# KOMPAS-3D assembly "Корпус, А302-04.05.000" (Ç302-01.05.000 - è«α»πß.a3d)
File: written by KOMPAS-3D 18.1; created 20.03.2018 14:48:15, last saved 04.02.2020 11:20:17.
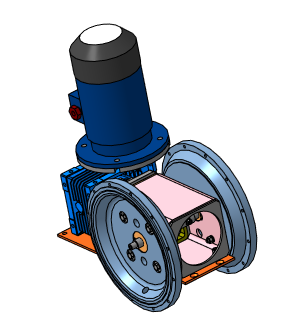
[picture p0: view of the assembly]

Document properties: Автор: Милов; Полное имя файла: D:\Мембранные насосы\Мембранный электропривод\А302-00.00.000 - ASTRA-302 (МЭ200) новая для Караби\3Д ПВХ\А302-01.05.000 - Корпус.a3d

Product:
- Part/product: Корпус  | designation А302-04.05.000  | pos. 0
    Масса: 37.0586
    Раздел спецификации: Сборочные единицы
    Форматы листов документа: A3
    source file: ..\А302-04.00.000 - Мембранный насос ASTRA-302-PP\А302-04.05.000 - Корпус.cdw
  - Component [standard]: Винт с потайной головкой и шестигранным углублением под ключГОСТ Р ИСО 10642-М4x20-8.8-A3J  | pos. 43  | Материал: Сталь (density 1000 kg/m3); Масса: 0.000288344; Раздел спецификации: Стандартные изделия; additional columns: ГОСТ Р ИСО 10642-2012; М4 x 20 - 8.8 - A3J; Сталь
  - Component [standard]: Винт с потайной головкой и шестигранным углублением под ключГОСТ Р ИСО 10642-М4x20-8.8-A3J  | pos. 42  | Материал: Сталь (density 1000 kg/m3); Масса: 0.000288344; Раздел спецификации: Стандартные изделия; additional columns: ГОСТ Р ИСО 10642-2012; М4 x 20 - 8.8 - A3J; Сталь
  - Component [standard]: Болт М8-6gx35.58.019 ГОСТ 7805-70  | qty 4  | pos. 8  | Материал: Сталь 20 ГОСТ 1050-2013 (density 1000 kg/m3); Масса: 0.01909; Раздел спецификации: Стандартные изделия; Рассекать на разрезах: no; additional columns: Сталь 20 ГОСТ 1050-2013
  - Component [detail]: Основание  | designation А302-04.05.001  | qty 2  | pos. 4  | Материал: Полипропилен  ГОСТ 26996-86 (density 900 kg/m3); Масса: 1.33492; Раздел спецификации: Детали; Форматы листов документа: A3; source file: ..\3Д\А302-00.05.001 - Основание.m3d, ..\А302-05.00.000 - Мембранный насос ASTRA-302-PVC\А302-05.05.001 - Основание.cdw, ..\Чертежи ПВХ\А302-02.05.001 - Основание.cdw, ..\Чертежи Полипропилен\А302-03.05.001 - Основание.cdw
  - Component [detail]: Ловитель  | designation А302-01.05.002  | qty 2  | pos. 5  | Материал: Фторопласт-4  ГОСТ 10007-80 Е (density 2200 kg/m3); Масса: 0.0582106; Раздел спецификации: Детали; Форматы листов документа: A3; source file: А302-01.05.002 - Ловитель.cdw, Отработка\А302-01.05.002 - Ловитель.m3d
  - Component [assembly]: Мотор-редуктор  | designation А302-04.20.000  | pos. 53  | Масса: 34.037; Раздел спецификации: Сборочные единицы; Форматы листов документа: A3; source file: ..\А302-04.00.000 - Мембранный насос ASTRA-302-PP\А302-04.20.000 СБ - Мотор-редуктор.cdw, Отработка\А302-01.20.000 - Мотор-редуктор.a3d
  - Component [standard]: Болт М8-6gx35.58.019 ГОСТ 7805-70  | pos. 457  | Материал: Сталь 20 ГОСТ 1050-2013 (density 1000 kg/m3); Масса: 0.01909; Раздел спецификации: Стандартные изделия; Рассекать на разрезах: no
  - Component [standard]: Болт М8-6gx35.58.019 ГОСТ 7805-70  | pos. 458  | Материал: Сталь 20 ГОСТ 1050-2013 (density 1000 kg/m3); Масса: 0.01909; Раздел спецификации: Стандартные изделия; Рассекать на разрезах: no
  - Component [standard]: Болт М8-6gx35.58.019 ГОСТ 7805-70  | pos. 459  | Материал: Сталь 20 ГОСТ 1050-2013 (density 1000 kg/m3); Масса: 0.01909; Раздел спецификации: Стандартные изделия; Рассекать на разрезах: no
  - Component [standard]: Болт М8-6gx35.58.019 ГОСТ 7805-70  | pos. 460  | Материал: Сталь 20 ГОСТ 1050-2013 (density 1000 kg/m3); Масса: 0.01909; Раздел спецификации: Стандартные изделия; Рассекать на разрезах: no
- Part/product: Корпус  | designation А302-03.05.000  | pos. 0
    Масса: 31.4728
    Раздел спецификации: Сборочные единицы
    Форматы листов документа: A3
    source file: ..\Чертежи Полипропилен\А302-03.05.000 - Корпус.cdw
  - Component [assembly]: Мотор-редуктор  | designation А302-02.20.000  | pos. 53  | Масса: 27.8186; Раздел спецификации: Сборочные единицы; Форматы листов документа: 2xA3; Примечание: @100~)2xA3; source file: Отработка\А302-01.20.000 - Мотор-редуктор.a3d
  - Component [detail]: Ловитель  | designation А302-01.05.002  | qty 2  | pos. 5  | Материал: Фторопласт-4  ГОСТ 10007-80 Е (density 2200 kg/m3); Масса: 0.0582106; Раздел спецификации: Детали; Форматы листов документа: A3; source file: А302-01.05.002 - Ловитель.cdw, Отработка\А302-01.05.002 - Ловитель.m3d
  - Component [detail]: Основание  | designation А302-03.05.001  | qty 2  | pos. 4  | Материал: Полипропилен  ГОСТ 26996-86 (density 900 kg/m3); Масса: 1.33086; Раздел спецификации: Детали; Форматы листов документа: A3; source file: ..\3Д\А302-00.05.001 - Основание.m3d
  - Component [detail]: Фиксатор  | designation А302-01.05.012  | pos. 1  | Раздел спецификации: Детали; Форматы листов документа: A3; source file: А302-01.05.012 - Фиксатор.cdw, Отработка\Фиксатор.m3d
  - Component [detail]: Упор  | designation А302-01.05.014  | qty 2  | pos. 1  | Материал: Сталь 20  ГОСТ 1050-2013 (density 0 kg/m3); Раздел спецификации: Детали; Форматы листов документа: A3; source file: А302-01.05.014 - Упор.cdw, Отработка\Упор-1.m3d
  - Component [detail]: Ловитель  | designation А302-01.05.011  | pos. 1  | Материал: Сталь 40  ГОСТ 1050-2013 (density 0 kg/m3); Раздел спецификации: Детали; Форматы листов документа: A4; source file: А302-01.05.011 - Ловитель.cdw, А302-01.05.011 - Ловитель.m3d
  - Component [detail]: Фиксатор  | designation А302-01.05.015  | pos. 198  | Раздел спецификации: Детали; Форматы листов документа: A4; source file: А302-01.05.015 - Фиксатор.cdw, А302-01.05.015 - Фиксатор.m3d
  - Component [detail]: Фиксатор  | designation А302-01.05.015  | pos. 189  | Раздел спецификации: Детали; Форматы листов документа: A4; source file: А302-01.05.015 - Фиксатор.cdw, А302-01.05.015 - Фиксатор.m3d
- Part/product: Корпус  | designation А302-00.05.000  | pos. 0
    Масса: 33.4594
    Раздел спецификации: Сборочные единицы
    Форматы листов документа: A3
  - Component [assembly]: Мотор-редуктор  | designation А302-01.20.000  | pos. 0  | Масса: 27.8253; Раздел спецификации: Сборочные единицы; Форматы листов документа: 2xA3; Примечание: @100~)2xA3; source file: А302-01.20.000 - Мотор-редуктор.cdw, Отработка\А302-01.20.000 - Мотор-редуктор.a3d
  - Component [detail]: Ловитель  | designation А302-01.05.002  | qty 2  | pos. 5  | Материал: Фторопласт-4  ГОСТ 10007-80 Е (density 2200 kg/m3); Масса: 0.0582106; Раздел спецификации: Детали; Форматы листов документа: A3; source file: А302-01.05.002 - Ловитель.cdw, Отработка\А302-01.05.002 - Ловитель.m3d
  - Component [detail]: Основание  | designation А302-00.05.001  | qty 2  | pos. 4  | Материал: Полипропилен  ГОСТ 26996-86 (density 900 kg/m3); Масса: 1.33086; Раздел спецификации: Детали; Форматы листов документа: A3; source file: ..\3Д\А302-00.05.001 - Основание.m3d, \\192.168.87.28\Konstructor_doc\Мембранные насосы\Мембранный электропривод\А302-00.00.000 - ASTRA-302 (МЭ200)\Чертежи\А302-00.05.001 - Основание.cdw
  - Component [standard]: Шайба C.8.21 ГОСТ 11371-78  | qty 12  | pos. 12  | Материал: Сталь 12Х18Н10Т ГОСТ 5632-72 (density 1000 kg/m3); Масса: 0.001725; Раздел спецификации: Стандартные изделия; additional columns: Сталь 12Х18Н10Т ГОСТ 5632-72; source file: C:\Program Files\ASCON\KOMPAS-3D v18\Libs\PartLib\DATA\VAULT\methods\kompas\3d\PLib_Washer_1_712.m3d
  - Component [standard]: Шайба C 8.04.019 ГОСТ 6958-78  | qty 12  | pos. 11  | Материал: Сталь 20 ГОСТ 1050-2013 (density 1000 kg/m3); Масса: 0.00610374; Раздел спецификации: Стандартные изделия; additional columns: Сталь 20 ГОСТ 1050-2013; source file: C:\Program Files\ASCON\KOMPAS-3D v18\Libs\PartLib\DATA\VAULT\methods\kompas\3d\PLib_Washer_1_712.m3d
  - Component [standard]: Шайба 8 30Х13 019 ГОСТ 6402-70  | qty 12  | pos. 10  | Материал: Сталь 30Х13 ГОСТ 5632-72 (density 1000 kg/m3); Масса: 0.001034; Раздел спецификации: Стандартные изделия; additional columns: Сталь 30Х13 ГОСТ 5632-72; source file: C:\Program Files\ASCON\KOMPAS-3D v18\Libs\PartLib\DATA\VAULT\methods\kompas\3d\PLib_Washer_2_712.m3d
  - Component [standard]: Болт М8-6gx30.58.019 ГОСТ 7805-70  | qty 12  | pos. 8  | Материал: Сталь 20 ГОСТ 1050-2013 (density 1000 kg/m3); Масса: 0.01712; Раздел спецификации: Стандартные изделия; additional columns: Сталь 20 ГОСТ 1050-2013; source file: C:\Program Files\ASCON\KOMPAS-3D v18\Libs\PartLib\DATA\VAULT\methods\kompas\3d\PLib_Bolt_1_900.m3d
  - Component [standard]: Гайка М8-6H.5.019 ГОСТ 5915-70  | qty 12  | pos. 9  | Масса: 0.005548; Раздел спецификации: Стандартные изделия; additional columns: Сталь 10 ГОСТ 1050-2013; source file: C:\Program Files\ASCON\KOMPAS-3D v18\Libs\PartLib\DATA\VAULT\methods\kompas\3d\PLib_Nut_OST92_900.m3d
  - Component [detail]: Подшипник 80х40х18 6208-2RS1 SKF  | pos. 0  | Масса: 0.504792; Раздел спецификации: Стандартные изделия; source file: ..\..\..\..\1 ПКИ 3D\1 Крепеж стандартный\Подшипник\Подшипник 80х40х18 6208-2RS1 SKF.m3d
  - Component [detail]: Фиксатор  | designation А302-01.05.012  | pos. 1  | Масса: 0.461484; Раздел спецификации: Детали; Форматы листов документа: A3; source file: А302-01.05.012 - Фиксатор.cdw, Отработка\Фиксатор.m3d
  - Component [detail]: Упор  | designation А302-01.05.014  | qty 2  | pos. 1  | Материал: Сталь 20  ГОСТ 1050-2013 (density 7820 kg/m3); Масса: 0.576984; Раздел спецификации: Детали; Форматы листов документа: A3; source file: А302-01.05.014 - Упор.cdw, Отработка\Упор-1.m3d
  - Component [detail]: Ловитель  | designation А302-01.05.011  | qty 4  | pos. 1  | Материал: Сталь 40  ГОСТ 1050-2013 (density 7820 kg/m3); Масса: 0.0202413; Раздел спецификации: Детали; Форматы листов документа: A4; source file: А302-01.05.011 - Ловитель.cdw, А302-01.05.011 - Ловитель.m3d
  - Component [standard]: Шайба C.5.21 ГОСТ 11371-78  | qty 4  | pos. 30  | Материал: Сталь 12Х18Н10Т ГОСТ 5632-72 (density 1000 kg/m3); Масса: 0.00043; Раздел спецификации: Стандартные изделия; additional columns: Сталь 12Х18Н10Т ГОСТ 5632-72; source file: C:\Program Files\ASCON\KOMPAS-3D v18\Libs\PartLib\DATA\VAULT\methods\kompas\3d\PLib_Washer_1_712.m3d
  - Component [standard]: Шайба 5 30Х13 019 ГОСТ 6402-70  | qty 4  | pos. 31  | Материал: Сталь 30Х13 ГОСТ 5632-72 (density 1000 kg/m3); Масса: 0.000228; Раздел спецификации: Стандартные изделия; additional columns: Сталь 30Х13 ГОСТ 5632-72; source file: C:\Program Files\ASCON\KOMPAS-3D v18\Libs\PartLib\DATA\VAULT\methods\kompas\3d\PLib_Washer_2_712.m3d
  - Component [standard]: Винт с цилиндрической головкой и шестигранным углублением под ключ ГОСТ Р ИСО  4762-М5 x 16-6.8-A9J  | qty 4  | pos. 32  | Материал: Сталь (density 1000 kg/m3); Масса: 0.00345; Раздел спецификации: Стандартные изделия; additional columns: ГОСТ Р ИСО 4762-2012; М5 x 16 - 6.8 - A9J; Сталь; source file: C:\Program Files\ASCON\KOMPAS-3D v18\Libs\PartLib\DATA\VAULT\methods\kompas\3d\PLib_Screw_DIN_7984_1500.m3d
  - Component [standard]: Шайба C.8.21 ГОСТ 11371-78  | qty 6  | pos. 33  | Материал: Сталь 12Х18Н10Т ГОСТ 5632-72 (density 1000 kg/m3); Масса: 0.001725; Раздел спецификации: Стандартные изделия; additional columns: Сталь 12Х18Н10Т ГОСТ 5632-72; source file: C:\Program Files\ASCON\KOMPAS-3D v18\Libs\PartLib\DATA\VAULT\methods\kompas\3d\PLib_Washer_1_712.m3d
  - Component [standard]: Шайба 8 30Х13 019 ГОСТ 6402-70  | qty 6  | pos. 34  | Материал: Сталь 30Х13 ГОСТ 5632-72 (density 1000 kg/m3); Масса: 0.001034; Раздел спецификации: Стандартные изделия; additional columns: Сталь 30Х13 ГОСТ 5632-72; source file: C:\Program Files\ASCON\KOMPAS-3D v18\Libs\PartLib\DATA\VAULT\methods\kompas\3d\PLib_Washer_2_712.m3d
  - Component [detail]: Фиксатор  | designation А302-01.05.012  | qty 4  | pos. 1  | Раздел спецификации: Детали; source file: А302-01.05.012 - Фиксатор.m3d
  - Component [standard]: Шайба C.5.21 ГОСТ 11371-78  | pos. 36  | Материал: Сталь 12Х18Н10Т ГОСТ 5632-72 (density 1000 kg/m3); Масса: 0.00043; Раздел спецификации: Стандартные изделия; additional columns: Сталь 12Х18Н10Т ГОСТ 5632-72; source file: C:\Program Files\ASCON\KOMPAS-3D v18\Libs\PartLib\DATA\VAULT\methods\kompas\3d\PLib_Washer_1_712.m3d
  - Component [standard]: Шайба C.5.21 ГОСТ 11371-78  | pos. 37  | Материал: Сталь 12Х18Н10Т ГОСТ 5632-72 (density 1000 kg/m3); Масса: 0.00043; Раздел спецификации: Стандартные изделия; additional columns: Сталь 12Х18Н10Т ГОСТ 5632-72; source file: C:\Program Files\ASCON\KOMPAS-3D v18\Libs\PartLib\DATA\VAULT\methods\kompas\3d\PLib_Washer_1_712.m3d
  - Component [standard]: Шайба 5 30Х13 019 ГОСТ 6402-70  | pos. 38  | Материал: Сталь 30Х13 ГОСТ 5632-72 (density 1000 kg/m3); Масса: 0.000228; Раздел спецификации: Стандартные изделия; additional columns: Сталь 30Х13 ГОСТ 5632-72; source file: C:\Program Files\ASCON\KOMPAS-3D v18\Libs\PartLib\DATA\VAULT\methods\kompas\3d\PLib_Washer_2_712.m3d
  - Component [standard]: Шайба 5 30Х13 019 ГОСТ 6402-70  | pos. 39  | Материал: Сталь 30Х13 ГОСТ 5632-72 (density 1000 kg/m3); Масса: 0.000228; Раздел спецификации: Стандартные изделия; additional columns: Сталь 30Х13 ГОСТ 5632-72; source file: C:\Program Files\ASCON\KOMPAS-3D v18\Libs\PartLib\DATA\VAULT\methods\kompas\3d\PLib_Washer_2_712.m3d
  - Component [standard]: Винт с цилиндрической головкой и шестигранным углублением под ключ ГОСТ Р ИСО  4762-М5 x 16-6.8-A9J  | pos. 40  | Материал: Сталь (density 1000 kg/m3); Масса: 0.00345; Раздел спецификации: Стандартные изделия; additional columns: ГОСТ Р ИСО 4762-2012; М5 x 16 - 6.8 - A9J; Сталь; source file: C:\Program Files\ASCON\KOMPAS-3D v18\Libs\PartLib\DATA\VAULT\methods\kompas\3d\PLib_Screw_DIN_7984_1500.m3d
  - Component [standard]: Винт с цилиндрической головкой и шестигранным углублением под ключ ГОСТ Р ИСО  4762-М5 x 12-6.8-A9J  | pos. 41  | Материал: Сталь (density 1000 kg/m3); Масса: 0.00295; Раздел спецификации: Стандартные изделия; additional columns: ГОСТ Р ИСО 4762-2012; М5 x 12 - 6.8 - A9J; Сталь; source file: C:\Program Files\ASCON\KOMPAS-3D v18\Libs\PartLib\DATA\VAULT\methods\kompas\3d\PLib_Screw_DIN_7984_1500.m3d
  - Component [standard]: Винт с цилиндрической головкой и шестигранным углублением под ключ ГОСТ Р ИСО  4762-М5 x 12-6.8-A9J  | pos. 41  | Материал: Сталь (density 1000 kg/m3); Масса: 0.00295; Раздел спецификации: Стандартные изделия; additional columns: ГОСТ Р ИСО 4762-2012; М5 x 12 - 6.8 - A9J; Сталь; source file: C:\Program Files\ASCON\KOMPAS-3D v18\Libs\PartLib\DATA\VAULT\methods\kompas\3d\PLib_Screw_DIN_7984_1500.m3d, C:\Users\User\AppData\Local\Temp\..\..\..\..\..\Program Files\ASCON\KOMPAS-3D V16\Libs\PartLib\DATA\vault\Methods\Kompas\3D\PLib_Screw_DIN_7984_1500.m3d
  - Component [standard]: Винт с цилиндрической головкой и шестигранным углублением под ключ ГОСТ Р ИСО  4762-М5 x 16-6.8-A9J  | pos. 40  | Материал: Сталь (density 1000 kg/m3); Масса: 0.00345; Раздел спецификации: Стандартные изделия; additional columns: ГОСТ Р ИСО 4762-2012; М5 x 16 - 6.8 - A9J; Сталь; source file: C:\Program Files\ASCON\KOMPAS-3D v18\Libs\PartLib\DATA\VAULT\methods\kompas\3d\PLib_Screw_DIN_7984_1500.m3d, C:\Users\User\AppData\Local\Temp\..\..\..\..\..\Program Files\ASCON\KOMPAS-3D V16\Libs\PartLib\DATA\vault\Methods\Kompas\3D\PLib_Screw_DIN_7984_1500.m3d
  - Component [standard]: Шайба 5 30Х13 019 ГОСТ 6402-70  | pos. 39  | Материал: Сталь 30Х13 ГОСТ 5632-72 (density 1000 kg/m3); Масса: 0.000228; Раздел спецификации: Стандартные изделия; additional columns: Сталь 30Х13 ГОСТ 5632-72; source file: C:\Program Files\ASCON\KOMPAS-3D v18\Libs\PartLib\DATA\VAULT\methods\kompas\3d\PLib_Washer_2_712.m3d, C:\Users\User\AppData\Local\Temp\..\..\..\..\..\Program Files\ASCON\KOMPAS-3D V16\Libs\PartLib\DATA\VAULT\Methods\kompas\3d\PLib_Washer_2_712.m3d
  - Component [standard]: Шайба 5 30Х13 019 ГОСТ 6402-70  | pos. 38  | Материал: Сталь 30Х13 ГОСТ 5632-72 (density 1000 kg/m3); Масса: 0.000228; Раздел спецификации: Стандартные изделия; additional columns: Сталь 30Х13 ГОСТ 5632-72; source file: C:\Program Files\ASCON\KOMPAS-3D v18\Libs\PartLib\DATA\VAULT\methods\kompas\3d\PLib_Washer_2_712.m3d, C:\Users\User\AppData\Local\Temp\..\..\..\..\..\Program Files\ASCON\KOMPAS-3D V16\Libs\PartLib\DATA\VAULT\Methods\kompas\3d\PLib_Washer_2_712.m3d
  - Component [standard]: Шайба C.5.21 ГОСТ 11371-78  | pos. 37  | Материал: Сталь 12Х18Н10Т ГОСТ 5632-72 (density 1000 kg/m3); Масса: 0.00043; Раздел спецификации: Стандартные изделия; additional columns: Сталь 12Х18Н10Т ГОСТ 5632-72; source file: C:\Program Files\ASCON\KOMPAS-3D v18\Libs\PartLib\DATA\VAULT\methods\kompas\3d\PLib_Washer_1_712.m3d, C:\Users\User\AppData\Local\Temp\..\..\..\..\..\Program Files\ASCON\KOMPAS-3D V16\Libs\PartLib\DATA\vault\Methods\Kompas\3D\PLib_Washer_1_712.m3d
  - Component [standard]: Шайба C.5.21 ГОСТ 11371-78  | pos. 36  | Материал: Сталь 12Х18Н10Т ГОСТ 5632-72 (density 1000 kg/m3); Масса: 0.00043; Раздел спецификации: Стандартные изделия; additional columns: Сталь 12Х18Н10Т ГОСТ 5632-72; source file: C:\Program Files\ASCON\KOMPAS-3D v18\Libs\PartLib\DATA\VAULT\methods\kompas\3d\PLib_Washer_1_712.m3d, C:\Users\User\AppData\Local\Temp\..\..\..\..\..\Program Files\ASCON\KOMPAS-3D V16\Libs\PartLib\DATA\vault\Methods\Kompas\3D\PLib_Washer_1_712.m3d
  - Component [standard]: Винт с потайной головкой и шестигранным углублением под ключ ГОСТ Р ИСО  10642-М4 x 20-8.8-A3J  | pos. 42  | Материал: Сталь (density 1000 kg/m3); Масса: 0.000288344; Раздел спецификации: Стандартные изделия; additional columns: ГОСТ Р ИСО 10642-2012; М4 x 20 - 8.8 - A3J; Сталь; source file: C:\Program Files\ASCON\KOMPAS-3D v18\Libs\PartLib\DATA\VAULT\methods\kompas\3d\PLib_Screw_ISO_10642_1500.m3d
  - Component [standard]: Винт с потайной головкой и шестигранным углублением под ключ ГОСТ Р ИСО  10642-М4 x 20-8.8-A3J  | pos. 43  | Материал: Сталь (density 1000 kg/m3); Масса: 0.000288344; Раздел спецификации: Стандартные изделия; additional columns: ГОСТ Р ИСО 10642-2012; М4 x 20 - 8.8 - A3J; Сталь; source file: C:\Program Files\ASCON\KOMPAS-3D v18\Libs\PartLib\DATA\VAULT\methods\kompas\3d\PLib_Screw_ISO_10642_1500.m3d
  - Component [standard]: Винт с цилиндрической головкой и шестигранным углублением под ключ ГОСТ Р ИСО  4762-М8 x 45-6.8-A9J  | qty 6  | pos. 44  | Материал: Сталь (density 1000 kg/m3); Масса: 0.0229; Раздел спецификации: Стандартные изделия; additional columns: ГОСТ Р ИСО 4762-2012; М8 x 45 - 6.8 - A9J; Сталь; source file: C:\Program Files\ASCON\KOMPAS-3D v18\Libs\PartLib\DATA\VAULT\methods\kompas\3d\PLib_Screw_DIN_7984_1500.m3d
  - Component [standard]: Шайба C.8.21 ГОСТ 11371-78  | qty 2  | pos. 45  | Материал: Сталь 12Х18Н10Т ГОСТ 5632-72 (density 1000 kg/m3); Масса: 0.001725; Раздел спецификации: Стандартные изделия; additional columns: Сталь 12Х18Н10Т ГОСТ 5632-72; source file: C:\Program Files\ASCON\KOMPAS-3D v18\Libs\PartLib\DATA\VAULT\methods\kompas\3d\PLib_Washer_1_712.m3d
  - Component [standard]: Шайба C.8.21 ГОСТ 11371-78  | qty 2  | pos. 46  | Материал: Сталь 12Х18Н10Т ГОСТ 5632-72 (density 1000 kg/m3); Масса: 0.001725; Раздел спецификации: Стандартные изделия; additional columns: Сталь 12Х18Н10Т ГОСТ 5632-72; source file: C:\Program Files\ASCON\KOMPAS-3D v18\Libs\PartLib\DATA\VAULT\methods\kompas\3d\PLib_Washer_1_712.m3d
  - Component [standard]: Шайба 8 30Х13 019 ГОСТ 6402-70  | qty 2  | pos. 47  | Материал: Сталь 30Х13 ГОСТ 5632-72 (density 1000 kg/m3); Масса: 0.001034; Раздел спецификации: Стандартные изделия; additional columns: Сталь 30Х13 ГОСТ 5632-72; source file: C:\Program Files\ASCON\KOMPAS-3D v18\Libs\PartLib\DATA\VAULT\methods\kompas\3d\PLib_Washer_2_712.m3d
  - Component [standard]: Шайба 8 30Х13 019 ГОСТ 6402-70  | qty 2  | pos. 48  | Материал: Сталь 30Х13 ГОСТ 5632-72 (density 1000 kg/m3); Масса: 0.001034; Раздел спецификации: Стандартные изделия; additional columns: Сталь 30Х13 ГОСТ 5632-72; source file: C:\Program Files\ASCON\KOMPAS-3D v18\Libs\PartLib\DATA\VAULT\methods\kompas\3d\PLib_Washer_2_712.m3d
  - Component [standard]: Винт с цилиндрической головкой и шестигранным углублением под ключ ГОСТ Р ИСО  4762-М8 x 35-6.8-A9J  | qty 2  | pos. 49  | Материал: Сталь (density 1000 kg/m3); Масса: 0.0189; Раздел спецификации: Стандартные изделия; additional columns: ГОСТ Р ИСО 4762-2012; М8 x 35 - 6.8 - A9J; Сталь; source file: C:\Program Files\ASCON\KOMPAS-3D v18\Libs\PartLib\DATA\VAULT\methods\kompas\3d\PLib_Screw_DIN_7984_1500.m3d
  - Component [standard]: Винт с цилиндрической головкой и шестигранным углублением под ключ ГОСТ Р ИСО  4762-М8 x 35-6.8-A9J  | qty 2  | pos. 50  | Материал: Сталь (density 1000 kg/m3); Масса: 0.0189; Раздел спецификации: Стандартные изделия; additional columns: ГОСТ Р ИСО 4762-2012; М8 x 35 - 6.8 - A9J; Сталь; source file: C:\Program Files\ASCON\KOMPAS-3D v18\Libs\PartLib\DATA\VAULT\methods\kompas\3d\PLib_Screw_DIN_7984_1500.m3d
  - Component [standard]: Кольцо A40.65Г ГОСТ 13942-86  | pos. 51  | Материал: Сталь 65Г ГОСТ 14959-79 (density 1000 kg/m3); Масса: 0.007267; Раздел спецификации: Стандартные изделия; additional columns: Сталь 65Г ГОСТ 14959-79; source file: C:\Program Files\ASCON\KOMPAS-3D v18\Libs\PartLib\DATA\VAULT\methods\kompas\3d\PLib_Check_spring_rings_GOST_13942_911.m3d
- Part/product: Корпус  | designation А302-02.05.000  | pos. 0
    Масса: 33.4489
    Раздел спецификации: Сборочные единицы
    Форматы листов документа: A3
  - Component [detail]: Ловитель  | designation А302-01.05.011  | qty 4  | pos. 1  | Материал: Сталь 40  ГОСТ 1050-2013 (density 7820 kg/m3); Масса: 0.0202413; Раздел спецификации: Детали; Форматы листов документа: A4; source file: А302-01.05.011 - Ловитель.cdw, А302-01.05.011 - Ловитель.m3d
  - Component [detail]: Упор  | designation А302-01.05.014  | qty 2  | pos. 1  | Материал: Сталь 20  ГОСТ 1050-2013 (density 7820 kg/m3); Масса: 0.576984; Раздел спецификации: Детали; Форматы листов документа: A3; source file: А302-01.05.014 - Упор.cdw, Отработка\Упор-1.m3d
  - Component [detail]: Фиксатор  | designation А302-01.05.012  | pos. 1  | Масса: 0.461484; Раздел спецификации: Детали; Форматы листов документа: A3; source file: А302-01.05.012 - Фиксатор.cdw, Отработка\Фиксатор.m3d
  - Component [detail]: Основание  | designation А302-00.05.001  | qty 2  | pos. 4  | Материал: Полипропилен  ГОСТ 26996-86 (density 900 kg/m3); Масса: 1.33086; Раздел спецификации: Детали; Форматы листов документа: A3; source file: ..\3Д\А302-00.05.001 - Основание.m3d, \\192.168.87.28\Konstructor_doc\Мембранные насосы\Мембранный электропривод\А302-00.00.000 - ASTRA-302 (МЭ200)\Чертежи\А302-00.05.001 - Основание.cdw
  - Component [detail]: Ловитель  | designation А302-01.05.002  | qty 2  | pos. 5  | Материал: Фторопласт-4  ГОСТ 10007-80 Е (density 2200 kg/m3); Масса: 0.0582106; Раздел спецификации: Детали; Форматы листов документа: A3; source file: А302-01.05.002 - Ловитель.cdw, Отработка\А302-01.05.002 - Ловитель.m3d
- Part/product: Корпус  | designation А302-05.05.000  | pos. 0
    Масса: 36.9667
    Раздел спецификации: Сборочные единицы
    Форматы листов документа: A3
  - Component [standard]: Болт М8-6gx35.58.019 ГОСТ 7805-70  | pos. 460  | Материал: Сталь 20 ГОСТ 1050-2013 (density 1000 kg/m3); Масса: 0.01909; Раздел спецификации: Стандартные изделия; Рассекать на разрезах: no
  - Component [standard]: Болт М8-6gx35.58.019 ГОСТ 7805-70  | pos. 459  | Материал: Сталь 20 ГОСТ 1050-2013 (density 1000 kg/m3); Масса: 0.01909; Раздел спецификации: Стандартные изделия; Рассекать на разрезах: no
  - Component [standard]: Болт М8-6gx35.58.019 ГОСТ 7805-70  | pos. 458  | Материал: Сталь 20 ГОСТ 1050-2013 (density 1000 kg/m3); Масса: 0.01909; Раздел спецификации: Стандартные изделия; Рассекать на разрезах: no
  - Component [standard]: Болт М8-6gx35.58.019 ГОСТ 7805-70  | pos. 457  | Материал: Сталь 20 ГОСТ 1050-2013 (density 1000 kg/m3); Масса: 0.01909; Раздел спецификации: Стандартные изделия; Рассекать на разрезах: no
  - Component [assembly]: Мотор-редуктор  | designation А302-04.20.000  | pos. 53  | Масса: 34.037; Раздел спецификации: Сборочные единицы; Форматы листов документа: A3; source file: ..\А302-04.00.000 - Мембранный насос ASTRA-302-PP\А302-04.20.000 СБ - Мотор-редуктор.cdw, Отработка\А302-01.20.000 - Мотор-редуктор.a3d
  - Component [detail]: Ловитель  | designation А302-01.05.002  | qty 2  | pos. 5  | Материал: Фторопласт-4  ГОСТ 10007-80 Е (density 2200 kg/m3); Масса: 0.0582106; Раздел спецификации: Детали; Форматы листов документа: A3; source file: А302-01.05.002 - Ловитель.cdw, Отработка\А302-01.05.002 - Ловитель.m3d
  - Component [detail]: Основание  | designation А302-05.05.001  | qty 2  | pos. 4  | Материал: Полипропилен  ГОСТ 26996-86 (density 900 kg/m3); Масса: 1.33492; Раздел спецификации: Детали; Форматы листов документа: A3
  - Component [standard]: Болт М8-6gx35.58.019 ГОСТ 7805-70  | qty 4  | pos. 8  | Материал: Сталь 20 ГОСТ 1050-2013 (density 1000 kg/m3); Масса: 0.01909; Раздел спецификации: Стандартные изделия; Рассекать на разрезах: no; additional columns: Сталь 20 ГОСТ 1050-2013
  - Component [standard]: Винт с потайной головкой и шестигранным углублением под ключГОСТ Р ИСО 10642-М4x20-8.8-A3J  | pos. 42  | Материал: Сталь (density 1000 kg/m3); Масса: 0.000288344; Раздел спецификации: Стандартные изделия; additional columns: ГОСТ Р ИСО 10642-2012; М4 x 20 - 8.8 - A3J; Сталь
  - Component [standard]: Винт с потайной головкой и шестигранным углублением под ключГОСТ Р ИСО 10642-М4x20-8.8-A3J  | pos. 43  | Материал: Сталь (density 1000 kg/m3); Масса: 0.000288344; Раздел спецификации: Стандартные изделия; additional columns: ГОСТ Р ИСО 10642-2012; М4 x 20 - 8.8 - A3J; Сталь

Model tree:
1. Массив по концентрической сетке:1  (with: Операция вращения:1)  (2 pattern instances)
     Шаг 2 = 360
2. Массив по концентрической сетке:2  (with: Операция вращения:1)  (4 pattern instances)
     Шаг 2 = 360
3. Массив по образцу:1  (4 pattern instances)
4. Массив по образцу:2
5. Экземпляр ( 1 )
6. Экземпляр ( 2 )
7. Массив по образцу:3  (6 pattern instances)
8. Массив по образцу:4  (with: Экземпляр ( 1 ), Экземпляр ( 2 ))
9. Сечение поверхностью:8
10. Сечение поверхностью:3
11. Сечение поверхностью:4  (with: Вырезать элемент выдавливания:6, Операция вращения:2, Вырезать элемент выдавливания:1, Отверстие:2, Вырезать элемент выдавливания:8, Операция выдавливания:1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)  (labels: Операция выдавливания:1; Операция выдавливания:1; Операция выдавливания:1; Операция выдавливания:1)
     Расстояние = 1; Расстояние = -5; Расстояние = -7; Расстояние = -0.8; Расстояние = -0.8
12. Эскиз:1  (with: Операция выдавливания:1, Фаска:2, Операция без истории:4, Вырезать элемент выдавливания:1, Вырезать элемент выдавливания:2)

Referenced files in D:\Мембранные насосы\Мембранный электропривод\А302-00.00.000 - ASTRA-302 (МЭ200) новая для Караби\3Д ПВХ\Отработка\: А302-01.20.000 - Мотор-редуктор.a3d, А302-01.05.002 - Ловитель.m3d, Фиксатор.m3d, Упор-1.m3d
Referenced files in D:\Мембранные насосы\Мембранный электропривод\А302-00.00.000 - ASTRA-302 (МЭ200) новая для Караби\3Д ПВХ\: А302-01.20.000 - Мотор-редуктор.cdw, А302-01.05.002 - Ловитель.cdw, А302-01.05.012 - Фиксатор.cdw, А302-01.05.014 - Упор.cdw, А302-01.05.011 - Ловитель.m3d, А302-01.05.011 - Ловитель.cdw, А302-01.05.012 - Фиксатор.m3d, А302-01.05.015 - Фиксатор.m3d, А302-01.05.015 - Фиксатор.cdw
Referenced files in D:\Мембранные насосы\Мембранный электропривод\А302-00.00.000 - ASTRA-302 (МЭ200) новая для Караби\3Д\: А302-00.05.001 - Основание.m3d
Referenced files in \\192.168.87.28\Konstructor_doc\Мембранные насосы\Мембранный электропривод\А302-00.00.000 - ASTRA-302 (МЭ200)\Чертежи\: А302-00.05.001 - Основание.cdw
Referenced files in C:\Program Files\ASCON\KOMPAS-3D v18\Libs\PartLib\DATA\VAULT\methods\kompas\3d\: PLib_Washer_1_712.m3d, PLib_Washer_2_712.m3d, PLib_Bolt_1_900.m3d, PLib_Nut_OST92_900.m3d, PLib_Screw_DIN_7984_1500.m3d, PLib_Screw_ISO_10642_1500.m3d, PLib_Check_spring_rings_GOST_13942_911.m3d
Referenced files in D:\1 ПКИ 3D\1 Крепеж стандартный\Подшипник\: Подшипник 80х40х18 6208-2RS1 SKF.m3d
Referenced files in D:\Мембранные насосы\Мембранный электропривод\А302-00.00.000 - ASTRA-302 (МЭ200) новая для Караби\3Д ПВХ\..\Чертежи ПВХ\: А302-02.05.001 - Основание.cdw
Referenced files in D:\Мембранные насосы\Мембранный электропривод\А302-00.00.000 - ASTRA-302 (МЭ200) новая для Караби\3Д ПВХ\..\Чертежи Полипропилен\: А302-03.05.001 - Основание.cdw
Referenced files in D:\Мембранные насосы\Мембранный электропривод\А302-00.00.000 - ASTRA-302 (МЭ200) новая для Караби\3Д ПВХ\..\А302-05.00.000 - Мембранный насос ASTRA-302-PVC\: А302-05.05.001 - Основание.cdw
Referenced files in D:\Мембранные насосы\Мембранный электропривод\А302-00.00.000 - ASTRA-302 (МЭ200) новая для Караби\3Д ПВХ\Отработка\..\..\А302-04.00.000 - Мембранный насос ASTRA-302-PP\: А302-04.20.000 СБ - Мотор-редуктор.cdw
Referenced files in D:\Мембранные насосы\Мембранный электропривод\А302-00.00.000 - ASTRA-302 (МЭ200) новая для Караби\А302-04.00.000 - Мембранный насос ASTRA-302-PP\: А302-04.20.000 СБ - Мотор-редуктор.cdw
Referenced files in D:\Мембранные насосы\Мембранный электропривод\А302-00.00.000 - ASTRA-302 (МЭ200)\3Д\: А302-00.05.001 - Основание.m3d
Referenced files in C:\Program Files\ASCON\KOMPAS-3D v18\Libs\PARTLib\DATA\vault\Methods\Kompas\3D\: PLib_Washer_2_712.m3d, PLib_Nut_OST92_900.m3d
Referenced files in D:\Мембранные насосы\Мембранный электропривод\А302-00.00.000 - ASTRA-302 (МЭ200)\3Д ПВХ\Отработка\: Упор-1.m3d, А302-01.05.002 - Ловитель.m3d, Фиксатор.m3d, А302-01.20.000 - Мотор-редуктор.a3d
Referenced files in D:\Мембранные насосы\Мембранный электропривод\А302-00.00.000 - ASTRA-302 (МЭ200)\3Д ПВХ\: А302-01.05.011 - Ловитель.m3d, А302-01.05.012 - Фиксатор.m3d, А302-01.05.015 - Фиксатор.m3d
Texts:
  @100~)2xA3
  Крепежное изделие ГОСТ
  Винт с цилиндрической головкой и шестигранным углублением под ключ
  Винт с потайной головкой и шестигранным углублением под ключ
  Винт с цилиндрической головкой и шестигранным углублением под ключГОСТ Р ИСО 4762-М8x45-6.8-A9J
  Винт с цилиндрической головкой и шестигранным углублением под ключГОСТ Р ИСО 4762-М5x16-6.8-A9J
  Винт с цилиндрической головкой и шестигранным углублением под ключГОСТ Р ИСО 4762-М8x35-6.8-A9J
  А302-04.20.000 СБ
  Точка начала. Х
  Точка начала. Y
  Точка начала. Z
  hole1
  hole2
  bcut1
  hcut1
  cut1
  Isp3
  А302-01.05.015 Фиксатор (1)
  А302-01.05.015 Фиксатор (2)
  Шайба C 8.04.019 ГОСТ 6958-78 (5)
  Шайба C 8.04.019 ГОСТ 6958-78 (6)
  Шайба C 8.04.019 ГОСТ 6958-78 (7)
  Шайба C 8.04.019 ГОСТ 6958-78 (8)
  Болт М8-6gx35.58.019 ГОСТ 7805-70 (5)
  Болт М8-6gx35.58.019 ГОСТ 7805-70 (6)
  Болт М8-6gx35.58.019 ГОСТ 7805-70 (7)
  Болт М8-6gx35.58.019 ГОСТ 7805-70 (8)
